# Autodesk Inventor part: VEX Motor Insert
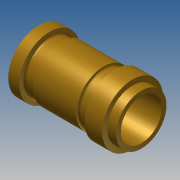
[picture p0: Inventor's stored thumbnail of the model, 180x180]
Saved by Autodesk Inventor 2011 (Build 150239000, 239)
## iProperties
Created: 2010-06
Part Number: VEX Motor Insert
Document SubType Name: Modeling
Designer: Phil
Density: 1 g/cm^3
Author: Phil
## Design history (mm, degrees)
sketch "Sketch1"
  geometry: L1 (6.1, 2.25)-(6.7, 2.25); L2 (6.9, 2.45)-(6.9, 2.75); L3 (8.5, 2.75)-(8.5, 2.275); L4 (9.3, 2.275)-(9.3, 1.859); L5 (8.5, 2.275)-(9.3, 2.275); L6 (6.9, 2.75)-(8.5, 2.75); L7 (5.9, 2.479)-(5.9, 2.45); L8 (2, 2.479)-(5.9, 2.479); L9 (9.3, 1.859)-(1, 1.859); L10 (2, 2.45)-(2, 2.479); L11 (1.2, 2.25)-(1.8, 2.25); L12 (1, 2.75)-(1, 2.45); L13 (1, 1.859)-(1, 1.359); L14 (1, 1.359)-(0.5, 0); L15 (0, 2.75)-(1, 2.75); L16 (0, 2.75)-(0, 0); L17 (0, 0)-(0.5, 0); L18 (1.138, 0)-(5.959, 0); A1 r 0.2 centre (6.7, 2.45) between (6.7, 2.25) and (6.9, 2.45); A2 r 0.2 centre (6.1, 2.45) between (5.9, 2.45) and (6.1, 2.25); A3 r 0.2 centre (1.8, 2.45) between (1.8, 2.25) and (2, 2.45); A4 r 0.2 centre (1.2, 2.45) between (1, 2.45) and (1.2, 2.25); 1 further point
  constraints: 36 end point, 8 point on circle, 4 centre point, 1 coincident, 1 collinear, 1 perpendicular
revolve "Revolution1" sketch "Sketch1" stored, may be unused: angle "d0" = 90 deg
body "Solid1"
